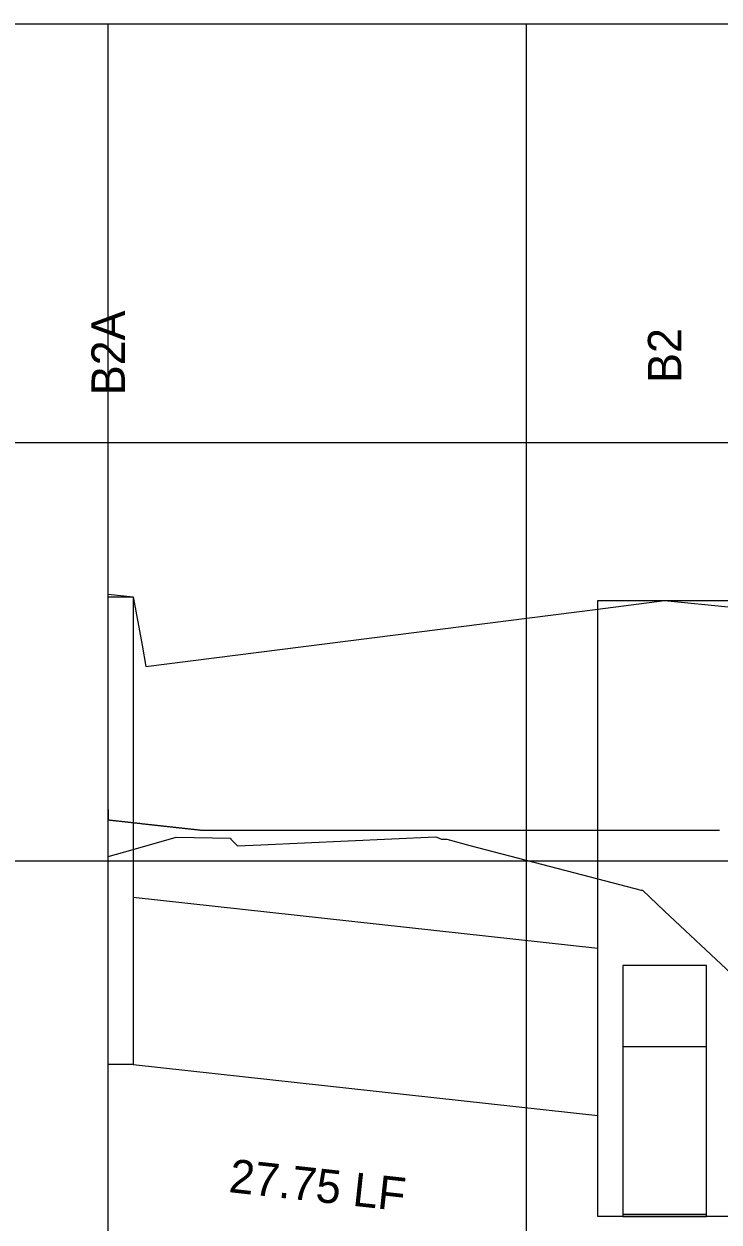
# Model space of a CAD drawing. Extents: x 2254979 to 2278074, y 13790855 to 13792793.
# Drawn here: x 2276869.4 to 2276910.9, y 13792721 to 13792792.6 of the extents above; entities that cross this region are included whole.
import ezdxf

# ---------------------------------------------------------------- set-up
doc = ezdxf.new("R2010")
doc.units = 0
for name, color, linetype in [('blank4', 7, 'Continuous'), ('BORD_grid_bottom_major_5int', 7, 'Continuous'), ('D_DRN_PROF_HGL', 7, 'Continuous'), ('D_PROF_1', 7, 'Continuous'), ('D_PROF_NOTES_1', 7, 'Continuous'), ('Drain_PipeInside', 7, 'Continuous'), ('E_Terrain', 7, 'Continuous'), ('Inlet', 7, 'Continuous'), ('z - Construction', 7, 'Continuous')]:
    doc.layers.add(name, color=color, linetype=linetype)

msp = doc.modelspace()

# ---------------------------------------------------------------- linework, layer by layer
at = {"layer": 'blank4'}
msp.add_lwpolyline([(2276874.404, 13792692.599), (2276874.404, 13792767.599), (2276944.852, 13792767.599), (2276944.852, 13792692.599)], close=True, dxfattribs=at)
at = {"layer": 'BORD_grid_bottom_major_5int'}
for p, q in [((2276749.404, 13792792.599), (2277074.404, 13792792.599)), ((2276874.404, 13792492.599), (2276874.404, 13792792.599)), ((2276899.404, 13792492.599), (2276899.404, 13792792.599)), ((2276749.404, 13792767.599), (2277074.404, 13792767.599)), ((2276749.404, 13792742.599), (2277074.404, 13792742.599))]:
    msp.add_line(p, q, dxfattribs=at)
at = {"layer": 'D_DRN_PROF_HGL'}
msp.add_line((2276907.654, 13792744.435), (2276907.654, 13792744.435), dxfattribs=at)
for points in [[(2276874.404, 13792745.671), (2276874.404, 13792745.042), (2276874.411, 13792745.046), (2276874.457, 13792745.041), (2276874.503, 13792745.036), (2276874.548, 13792745.031), (2276874.594, 13792745.026), (2276874.639, 13792745.021), (2276874.685, 13792745.016), (2276874.73, 13792745.011), (2276874.776, 13792745.006), (2276874.821, 13792745.001), (2276874.867, 13792744.996), (2276874.912, 13792744.991), (2276874.958, 13792744.986), (2276875.003, 13792744.981), (2276875.049, 13792744.975), (2276875.095, 13792744.97), (2276875.14, 13792744.965), (2276875.186, 13792744.96), (2276875.231, 13792744.955), (2276875.277, 13792744.95), (2276875.322, 13792744.945), (2276875.368, 13792744.94), (2276875.413, 13792744.935), (2276875.459, 13792744.93), (2276875.504, 13792744.925), (2276875.55, 13792744.92), (2276875.595, 13792744.915), (2276875.641, 13792744.91), (2276875.687, 13792744.905), (2276875.732, 13792744.9), (2276875.778, 13792744.895), (2276875.823, 13792744.89), (2276875.869, 13792744.885), (2276875.914, 13792744.88), (2276875.96, 13792744.875), (2276876.005, 13792744.87), (2276876.051, 13792744.865), (2276876.096, 13792744.86), (2276876.142, 13792744.855), (2276876.187, 13792744.85), (2276876.233, 13792744.845), (2276876.279, 13792744.84), (2276876.324, 13792744.835), (2276876.37, 13792744.83), (2276876.415, 13792744.825), (2276876.461, 13792744.82), (2276876.506, 13792744.815), (2276876.552, 13792744.81), (2276876.597, 13792744.805), (2276876.643, 13792744.8), (2276876.688, 13792744.795), (2276876.734, 13792744.79), (2276876.779, 13792744.785), (2276876.825, 13792744.78), (2276876.871, 13792744.775), (2276876.916, 13792744.77), (2276876.962, 13792744.765), (2276877.007, 13792744.76), (2276877.053, 13792744.755), (2276877.098, 13792744.75), (2276877.144, 13792744.745), (2276877.189, 13792744.74), (2276877.235, 13792744.735), (2276877.28, 13792744.73), (2276877.326, 13792744.725), (2276877.371, 13792744.72), (2276877.417, 13792744.715), (2276877.463, 13792744.71), (2276877.508, 13792744.704), (2276877.554, 13792744.699), (2276877.599, 13792744.694), (2276877.645, 13792744.689), (2276877.69, 13792744.684), (2276877.736, 13792744.679), (2276877.781, 13792744.674), (2276877.827, 13792744.669), (2276877.872, 13792744.664), (2276877.918, 13792744.659), (2276877.963, 13792744.654), (2276878.009, 13792744.649), (2276878.055, 13792744.644), (2276878.1, 13792744.639), (2276878.146, 13792744.634), (2276878.191, 13792744.629), (2276878.237, 13792744.624), (2276878.282, 13792744.619), (2276878.328, 13792744.614), (2276878.373, 13792744.609), (2276878.419, 13792744.604), (2276878.464, 13792744.599), (2276878.51, 13792744.594), (2276878.555, 13792744.589), (2276878.601, 13792744.584), (2276878.647, 13792744.579), (2276878.692, 13792744.574), (2276878.738, 13792744.569), (2276878.783, 13792744.564), (2276878.829, 13792744.559), (2276878.874, 13792744.554), (2276878.92, 13792744.549), (2276878.965, 13792744.544), (2276879.011, 13792744.539), (2276879.056, 13792744.534), (2276879.102, 13792744.529), (2276879.147, 13792744.524), (2276879.193, 13792744.519), (2276879.239, 13792744.514), (2276879.284, 13792744.509), (2276879.33, 13792744.504), (2276879.375, 13792744.499), (2276879.421, 13792744.494), (2276879.466, 13792744.489), (2276879.512, 13792744.484), (2276879.557, 13792744.479), (2276879.603, 13792744.474), (2276879.648, 13792744.469), (2276879.694, 13792744.464), (2276879.739, 13792744.459), (2276879.785, 13792744.454), (2276879.831, 13792744.449), (2276879.876, 13792744.444), (2276879.922, 13792744.44), (2276879.967, 13792744.44), (2276880.013, 13792744.44), (2276880.058, 13792744.44), (2276880.104, 13792744.44), (2276880.149, 13792744.44), (2276880.195, 13792744.44), (2276880.24, 13792744.44), (2276880.286, 13792744.44), (2276880.331, 13792744.44), (2276880.377, 13792744.44), (2276880.423, 13792744.44), (2276880.468, 13792744.44), (2276880.514, 13792744.44), (2276880.559, 13792744.44), (2276880.605, 13792744.44), (2276880.65, 13792744.44), (2276880.696, 13792744.44), (2276880.741, 13792744.44), (2276880.787, 13792744.44), (2276880.832, 13792744.44), (2276880.878, 13792744.44), (2276880.923, 13792744.44), (2276880.969, 13792744.44), (2276881.015, 13792744.44), (2276881.06, 13792744.44), (2276881.106, 13792744.44), (2276881.151, 13792744.44), (2276881.197, 13792744.44), (2276881.242, 13792744.44), (2276881.288, 13792744.44), (2276881.333, 13792744.44), (2276881.379, 13792744.44), (2276881.424, 13792744.44), (2276881.47, 13792744.44), (2276881.515, 13792744.44), (2276881.561, 13792744.44), (2276881.607, 13792744.44), (2276881.652, 13792744.44), (2276881.698, 13792744.44), (2276881.743, 13792744.44), (2276881.789, 13792744.44), (2276881.834, 13792744.44), (2276881.88, 13792744.44), (2276881.925, 13792744.44), (2276881.971, 13792744.44), (2276882.016, 13792744.44), (2276882.062, 13792744.44), (2276882.107, 13792744.44), (2276882.153, 13792744.44), (2276882.199, 13792744.44), (2276882.244, 13792744.44), (2276882.29, 13792744.44), (2276882.335, 13792744.44), (2276882.381, 13792744.44), (2276882.426, 13792744.44), (2276882.472, 13792744.44), (2276882.517, 13792744.44), (2276882.563, 13792744.44), (2276882.608, 13792744.44), (2276882.654, 13792744.44), (2276882.699, 13792744.44), (2276882.745, 13792744.44), (2276882.791, 13792744.44), (2276882.836, 13792744.44), (2276882.882, 13792744.44), (2276882.927, 13792744.44), (2276882.973, 13792744.44), (2276883.018, 13792744.44), (2276883.064, 13792744.44), (2276883.109, 13792744.44), (2276883.155, 13792744.44), (2276883.2, 13792744.44), (2276883.246, 13792744.44), (2276883.291, 13792744.44), (2276883.337, 13792744.44), (2276883.383, 13792744.44), (2276883.428, 13792744.44), (2276883.474, 13792744.44), (2276883.519, 13792744.44), (2276883.565, 13792744.44), (2276883.61, 13792744.44), (2276883.656, 13792744.44), (2276883.701, 13792744.44), (2276883.747, 13792744.44), (2276883.792, 13792744.44), (2276883.838, 13792744.44), (2276883.883, 13792744.44), (2276883.929, 13792744.44), (2276883.975, 13792744.44), (2276884.02, 13792744.44), (2276884.066, 13792744.44), (2276884.111, 13792744.44), (2276884.157, 13792744.44), (2276884.202, 13792744.44), (2276884.248, 13792744.44), (2276884.293, 13792744.44), (2276884.339, 13792744.44), (2276884.384, 13792744.44), (2276884.43, 13792744.439), (2276884.475, 13792744.439), (2276884.521, 13792744.439), (2276884.567, 13792744.439), (2276884.612, 13792744.439), (2276884.658, 13792744.439), (2276884.703, 13792744.439), (2276884.749, 13792744.439), (2276884.794, 13792744.439), (2276884.84, 13792744.439), (2276884.885, 13792744.439), (2276884.931, 13792744.439), (2276884.976, 13792744.439), (2276885.022, 13792744.439), (2276885.067, 13792744.439), (2276885.113, 13792744.439), (2276885.159, 13792744.439), (2276885.204, 13792744.439), (2276885.25, 13792744.439), (2276885.295, 13792744.439), (2276885.341, 13792744.439), (2276885.386, 13792744.439), (2276885.432, 13792744.439), (2276885.477, 13792744.439), (2276885.523, 13792744.439), (2276885.568, 13792744.439), (2276885.614, 13792744.439), (2276885.659, 13792744.439), (2276885.705, 13792744.439), (2276885.75, 13792744.439), (2276885.796, 13792744.439), (2276885.842, 13792744.439), (2276885.887, 13792744.439), (2276885.933, 13792744.439), (2276885.978, 13792744.439), (2276886.024, 13792744.439), (2276886.069, 13792744.439), (2276886.115, 13792744.439), (2276886.16, 13792744.439), (2276886.206, 13792744.439), (2276886.251, 13792744.439), (2276886.297, 13792744.439), (2276886.342, 13792744.439), (2276886.388, 13792744.439), (2276886.434, 13792744.439), (2276886.479, 13792744.439), (2276886.525, 13792744.439), (2276886.57, 13792744.439), (2276886.616, 13792744.439), (2276886.661, 13792744.439), (2276886.707, 13792744.439), (2276886.752, 13792744.439), (2276886.798, 13792744.439), (2276886.843, 13792744.439), (2276886.889, 13792744.439), (2276886.934, 13792744.439), (2276886.98, 13792744.439), (2276887.026, 13792744.439), (2276887.071, 13792744.439), (2276887.117, 13792744.439), (2276887.162, 13792744.439), (2276887.208, 13792744.439), (2276887.253, 13792744.439), (2276887.299, 13792744.439), (2276887.344, 13792744.439), (2276887.39, 13792744.439), (2276887.435, 13792744.439), (2276887.481, 13792744.439), (2276887.526, 13792744.439), (2276887.572, 13792744.439), (2276887.618, 13792744.439), (2276887.663, 13792744.439), (2276887.709, 13792744.439), (2276887.754, 13792744.439), (2276887.8, 13792744.439), (2276887.845, 13792744.439), (2276887.891, 13792744.439), (2276887.936, 13792744.439), (2276887.982, 13792744.439), (2276888.027, 13792744.439), (2276888.073, 13792744.439), (2276888.118, 13792744.439), (2276888.164, 13792744.439), (2276888.21, 13792744.439), (2276888.255, 13792744.439), (2276888.301, 13792744.439), (2276888.346, 13792744.439), (2276888.392, 13792744.439), (2276888.437, 13792744.439), (2276888.483, 13792744.439), (2276888.528, 13792744.439), (2276888.574, 13792744.439), (2276888.619, 13792744.439), (2276888.665, 13792744.439), (2276888.71, 13792744.439), (2276888.756, 13792744.439), (2276888.802, 13792744.439), (2276888.847, 13792744.439), (2276888.893, 13792744.439), (2276888.938, 13792744.439), (2276888.984, 13792744.439), (2276889.029, 13792744.439), (2276889.075, 13792744.439), (2276889.12, 13792744.439), (2276889.166, 13792744.439), (2276889.211, 13792744.439), (2276889.257, 13792744.439), (2276889.302, 13792744.439), (2276889.348, 13792744.438), (2276889.394, 13792744.438), (2276889.439, 13792744.438), (2276889.485, 13792744.438), (2276889.53, 13792744.438), (2276889.576, 13792744.438), (2276889.621, 13792744.438), (2276889.667, 13792744.438), (2276889.712, 13792744.438), (2276889.758, 13792744.438), (2276889.803, 13792744.438), (2276889.849, 13792744.438), (2276889.894, 13792744.438), (2276889.94, 13792744.438), (2276889.986, 13792744.438), (2276890.031, 13792744.438), (2276890.077, 13792744.438), (2276890.122, 13792744.438), (2276890.168, 13792744.438), (2276890.213, 13792744.438), (2276890.259, 13792744.438), (2276890.304, 13792744.438), (2276890.35, 13792744.438), (2276890.395, 13792744.438), (2276890.441, 13792744.438), (2276890.486, 13792744.438), (2276890.532, 13792744.438), (2276890.578, 13792744.438), (2276890.623, 13792744.438), (2276890.669, 13792744.438), (2276890.714, 13792744.438), (2276890.76, 13792744.438), (2276890.805, 13792744.438), (2276890.851, 13792744.438), (2276890.896, 13792744.438), (2276890.942, 13792744.438), (2276890.987, 13792744.438), (2276891.033, 13792744.438), (2276891.078, 13792744.438), (2276891.124, 13792744.438), (2276891.17, 13792744.438), (2276891.215, 13792744.438), (2276891.261, 13792744.438), (2276891.306, 13792744.438), (2276891.352, 13792744.438), (2276891.397, 13792744.438), (2276891.443, 13792744.438), (2276891.488, 13792744.438), (2276891.534, 13792744.438), (2276891.579, 13792744.438), (2276891.625, 13792744.438), (2276891.67, 13792744.438), (2276891.716, 13792744.438), (2276891.762, 13792744.438), (2276891.807, 13792744.438), (2276891.853, 13792744.438), (2276891.898, 13792744.438), (2276891.944, 13792744.438), (2276891.989, 13792744.438), (2276892.035, 13792744.438), (2276892.08, 13792744.438), (2276892.126, 13792744.438), (2276892.171, 13792744.438), (2276892.217, 13792744.438), (2276892.262, 13792744.438), (2276892.308, 13792744.438), (2276892.354, 13792744.438), (2276892.399, 13792744.438), (2276892.445, 13792744.438), (2276892.49, 13792744.438), (2276892.536, 13792744.438), (2276892.581, 13792744.438), (2276892.627, 13792744.438), (2276892.672, 13792744.438), (2276892.718, 13792744.438), (2276892.763, 13792744.438), (2276892.809, 13792744.438), (2276892.854, 13792744.438), (2276892.9, 13792744.438), (2276892.946, 13792744.438), (2276892.991, 13792744.438), (2276893.037, 13792744.438), (2276893.082, 13792744.438), (2276893.128, 13792744.438), (2276893.173, 13792744.438), (2276893.219, 13792744.438), (2276893.264, 13792744.438), (2276893.31, 13792744.438), (2276893.355, 13792744.438), (2276893.401, 13792744.438), (2276893.446, 13792744.438), (2276893.492, 13792744.438), (2276893.538, 13792744.438), (2276893.583, 13792744.438), (2276893.629, 13792744.438), (2276893.674, 13792744.438), (2276893.72, 13792744.438), (2276893.765, 13792744.438), (2276893.811, 13792744.438), (2276893.856, 13792744.438), (2276893.902, 13792744.438), (2276893.947, 13792744.438), (2276893.993, 13792744.438), (2276894.038, 13792744.438), (2276894.084, 13792744.438), (2276894.13, 13792744.438), (2276894.175, 13792744.438), (2276894.221, 13792744.438), (2276894.266, 13792744.437), (2276894.312, 13792744.437), (2276894.357, 13792744.437), (2276894.403, 13792744.437), (2276894.448, 13792744.437), (2276894.494, 13792744.437), (2276894.539, 13792744.437), (2276894.585, 13792744.437), (2276894.63, 13792744.437), (2276894.676, 13792744.437), (2276894.722, 13792744.437), (2276894.767, 13792744.437), (2276894.813, 13792744.437), (2276894.858, 13792744.437), (2276894.904, 13792744.437), (2276894.949, 13792744.437), (2276894.995, 13792744.437), (2276895.04, 13792744.437), (2276895.086, 13792744.437), (2276895.131, 13792744.437), (2276895.177, 13792744.437), (2276895.222, 13792744.437), (2276895.268, 13792744.437), (2276895.314, 13792744.437), (2276895.359, 13792744.437), (2276895.405, 13792744.437), (2276895.45, 13792744.437), (2276895.496, 13792744.437), (2276895.541, 13792744.437), (2276895.587, 13792744.437), (2276895.632, 13792744.437), (2276895.678, 13792744.437), (2276895.723, 13792744.437), (2276895.769, 13792744.437), (2276895.814, 13792744.437), (2276895.86, 13792744.437), (2276895.906, 13792744.437), (2276895.951, 13792744.437), (2276895.997, 13792744.437), (2276896.042, 13792744.437), (2276896.088, 13792744.437), (2276896.133, 13792744.437), (2276896.179, 13792744.437), (2276896.224, 13792744.437), (2276896.27, 13792744.437), (2276896.315, 13792744.437), (2276896.361, 13792744.437), (2276896.406, 13792744.437), (2276896.452, 13792744.437), (2276896.498, 13792744.437), (2276896.543, 13792744.437), (2276896.589, 13792744.437), (2276896.634, 13792744.437), (2276896.68, 13792744.437), (2276896.725, 13792744.437), (2276896.771, 13792744.437), (2276896.816, 13792744.437), (2276896.862, 13792744.437), (2276896.907, 13792744.437), (2276896.953, 13792744.437), (2276896.998, 13792744.437), (2276897.044, 13792744.437), (2276897.09, 13792744.437), (2276897.135, 13792744.437), (2276897.181, 13792744.437), (2276897.226, 13792744.437), (2276897.272, 13792744.437), (2276897.317, 13792744.437), (2276897.363, 13792744.437), (2276897.408, 13792744.437), (2276897.454, 13792744.437), (2276897.499, 13792744.437), (2276897.545, 13792744.437), (2276897.59, 13792744.437), (2276897.636, 13792744.437), (2276897.682, 13792744.437), (2276897.727, 13792744.437), (2276897.773, 13792744.437), (2276897.818, 13792744.437), (2276897.864, 13792744.437), (2276897.909, 13792744.437), (2276897.955, 13792744.437), (2276898, 13792744.437), (2276898.046, 13792744.437), (2276898.091, 13792744.437), (2276898.137, 13792744.437), (2276898.182, 13792744.437), (2276898.228, 13792744.437), (2276898.274, 13792744.437), (2276898.319, 13792744.437), (2276898.365, 13792744.437), (2276898.41, 13792744.437), (2276898.456, 13792744.437), (2276898.501, 13792744.437), (2276898.547, 13792744.437), (2276898.592, 13792744.437), (2276898.638, 13792744.437), (2276898.683, 13792744.437), (2276898.729, 13792744.437), (2276898.774, 13792744.437), (2276898.82, 13792744.437), (2276898.866, 13792744.437), (2276898.911, 13792744.437), (2276898.957, 13792744.437), (2276899.002, 13792744.437), (2276899.048, 13792744.437), (2276899.093, 13792744.437), (2276899.139, 13792744.437), (2276899.184, 13792744.436), (2276899.23, 13792744.436), (2276899.275, 13792744.436), (2276899.321, 13792744.436), (2276899.366, 13792744.436), (2276899.412, 13792744.436), (2276899.458, 13792744.436), (2276899.503, 13792744.436), (2276899.549, 13792744.436), (2276899.594, 13792744.436), (2276899.64, 13792744.436), (2276899.685, 13792744.436), (2276899.731, 13792744.436), (2276899.776, 13792744.436), (2276899.822, 13792744.436), (2276899.867, 13792744.436), (2276899.913, 13792744.436), (2276899.958, 13792744.436), (2276900.004, 13792744.436), (2276900.05, 13792744.436), (2276900.095, 13792744.436), (2276900.141, 13792744.436), (2276900.186, 13792744.436), (2276900.232, 13792744.436), (2276900.277, 13792744.436), (2276900.323, 13792744.436), (2276900.368, 13792744.436), (2276900.414, 13792744.436), (2276900.459, 13792744.436), (2276900.505, 13792744.436), (2276900.55, 13792744.436), (2276900.596, 13792744.436), (2276900.642, 13792744.436), (2276900.687, 13792744.436), (2276900.733, 13792744.436), (2276900.778, 13792744.436), (2276900.824, 13792744.436), (2276900.869, 13792744.436), (2276900.915, 13792744.436), (2276900.96, 13792744.436), (2276901.006, 13792744.436), (2276901.051, 13792744.436), (2276901.097, 13792744.436), (2276901.142, 13792744.436), (2276901.188, 13792744.436), (2276901.233, 13792744.436), (2276901.279, 13792744.436), (2276901.325, 13792744.436), (2276901.37, 13792744.436), (2276901.416, 13792744.436), (2276901.461, 13792744.436), (2276901.507, 13792744.436), (2276901.552, 13792744.436), (2276901.598, 13792744.436), (2276901.643, 13792744.436), (2276901.689, 13792744.436), (2276901.734, 13792744.436), (2276901.78, 13792744.436), (2276901.825, 13792744.436), (2276901.871, 13792744.436), (2276901.917, 13792744.436), (2276901.962, 13792744.436), (2276902.008, 13792744.436), (2276902.053, 13792744.436), (2276902.099, 13792744.436), (2276902.144, 13792744.436), (2276902.19, 13792744.436), (2276902.235, 13792744.436), (2276902.281, 13792744.436), (2276902.326, 13792744.436), (2276902.372, 13792744.436), (2276902.417, 13792744.436), (2276902.463, 13792744.436), (2276902.509, 13792744.436), (2276902.554, 13792744.436), (2276902.6, 13792744.436), (2276902.645, 13792744.436), (2276902.691, 13792744.436), (2276902.736, 13792744.436), (2276902.782, 13792744.436), (2276902.827, 13792744.436), (2276902.873, 13792744.436), (2276902.918, 13792744.436), (2276902.964, 13792744.436), (2276903.009, 13792744.436), (2276903.055, 13792744.436), (2276903.101, 13792744.436), (2276903.146, 13792744.436), (2276903.192, 13792744.436), (2276903.237, 13792744.436), (2276903.283, 13792744.436), (2276903.328, 13792744.436), (2276903.374, 13792744.436), (2276903.419, 13792744.436), (2276903.465, 13792744.436), (2276903.51, 13792744.436), (2276903.556, 13792744.436), (2276903.601, 13792744.436), (2276903.647, 13792744.436), (2276903.693, 13792744.436), (2276903.738, 13792744.436), (2276903.784, 13792744.436), (2276903.829, 13792744.436), (2276903.875, 13792744.436), (2276903.92, 13792744.436), (2276903.966, 13792744.436), (2276904.011, 13792744.435), (2276904.057, 13792744.435), (2276904.102, 13792744.435), (2276904.148, 13792744.435), (2276904.193, 13792744.435), (2276904.239, 13792744.435), (2276904.285, 13792744.435), (2276904.33, 13792744.435), (2276904.376, 13792744.435), (2276904.421, 13792744.435), (2276904.467, 13792744.435), (2276904.512, 13792744.435), (2276904.558, 13792744.435), (2276904.603, 13792744.435), (2276904.649, 13792744.435), (2276904.694, 13792744.435), (2276904.74, 13792744.435), (2276904.785, 13792744.435), (2276904.831, 13792744.435), (2276904.877, 13792744.435), (2276904.922, 13792744.435), (2276904.968, 13792744.435), (2276905.013, 13792744.435), (2276905.059, 13792744.435), (2276905.104, 13792744.435), (2276905.15, 13792744.435), (2276905.195, 13792744.435), (2276905.241, 13792744.435), (2276905.286, 13792744.435), (2276905.332, 13792744.435), (2276905.377, 13792744.435), (2276905.423, 13792744.435), (2276905.469, 13792744.435), (2276905.514, 13792744.435), (2276905.56, 13792744.435), (2276905.605, 13792744.435), (2276905.651, 13792744.435), (2276905.696, 13792744.435), (2276905.742, 13792744.435), (2276905.787, 13792744.435), (2276905.833, 13792744.435), (2276905.878, 13792744.435), (2276905.924, 13792744.435), (2276905.969, 13792744.435), (2276906.015, 13792744.435), (2276906.061, 13792744.435), (2276906.106, 13792744.435), (2276906.152, 13792744.435), (2276906.197, 13792744.435), (2276906.243, 13792744.435), (2276906.288, 13792744.435), (2276906.334, 13792744.435), (2276906.379, 13792744.435), (2276906.425, 13792744.435), (2276906.47, 13792744.435), (2276906.516, 13792744.435), (2276906.561, 13792744.435), (2276906.607, 13792744.435), (2276906.653, 13792744.435), (2276906.698, 13792744.435), (2276906.744, 13792744.435), (2276906.789, 13792744.435), (2276906.835, 13792744.435), (2276906.88, 13792744.435), (2276906.926, 13792744.435), (2276906.971, 13792744.435), (2276907.017, 13792744.435), (2276907.062, 13792744.435), (2276907.108, 13792744.435), (2276907.153, 13792744.435), (2276907.199, 13792744.435), (2276907.245, 13792744.435), (2276907.29, 13792744.435), (2276907.336, 13792744.435), (2276907.381, 13792744.435), (2276907.427, 13792744.435), (2276907.472, 13792744.435), (2276907.518, 13792744.435), (2276907.563, 13792744.435), (2276907.609, 13792744.435), (2276907.654, 13792744.435)], [(2276907.654, 13792744.435), (2276907.7, 13792744.435), (2276907.746, 13792744.435), (2276907.791, 13792744.435), (2276907.837, 13792744.435), (2276907.882, 13792744.435), (2276907.928, 13792744.435), (2276907.974, 13792744.435), (2276908.019, 13792744.435), (2276908.065, 13792744.435), (2276908.111, 13792744.435), (2276908.156, 13792744.435), (2276908.202, 13792744.435), (2276908.247, 13792744.435), (2276908.293, 13792744.435), (2276908.339, 13792744.435), (2276908.384, 13792744.435), (2276908.43, 13792744.435), (2276908.475, 13792744.435), (2276908.521, 13792744.435), (2276908.567, 13792744.435), (2276908.612, 13792744.435), (2276908.658, 13792744.435), (2276908.704, 13792744.435), (2276908.749, 13792744.435), (2276908.795, 13792744.435), (2276908.84, 13792744.435), (2276908.886, 13792744.435), (2276908.932, 13792744.435), (2276908.977, 13792744.435), (2276909.023, 13792744.435), (2276909.068, 13792744.435), (2276909.114, 13792744.435), (2276909.16, 13792744.435), (2276909.205, 13792744.435), (2276909.251, 13792744.435), (2276909.297, 13792744.435), (2276909.342, 13792744.435), (2276909.388, 13792744.435), (2276909.433, 13792744.435), (2276909.479, 13792744.435), (2276909.525, 13792744.435), (2276909.57, 13792744.436), (2276909.616, 13792744.436), (2276909.661, 13792744.436), (2276909.707, 13792744.436), (2276909.753, 13792744.436), (2276909.798, 13792744.436), (2276909.844, 13792744.436), (2276909.89, 13792744.436), (2276909.935, 13792744.436), (2276909.981, 13792744.436), (2276910.026, 13792744.436), (2276910.072, 13792744.436), (2276910.118, 13792744.436), (2276910.163, 13792744.436), (2276910.209, 13792744.436), (2276910.254, 13792744.436), (2276910.3, 13792744.436), (2276910.346, 13792744.436), (2276910.391, 13792744.436), (2276910.437, 13792744.436), (2276910.483, 13792744.436), (2276910.528, 13792744.436), (2276910.574, 13792744.436), (2276910.619, 13792744.436), (2276910.665, 13792744.436), (2276910.711, 13792744.436), (2276910.756, 13792744.436), (2276910.802, 13792744.436), (2276910.847, 13792744.436), (2276910.893, 13792744.436), (2276910.939, 13792744.436)]]:
    msp.add_lwpolyline(points, dxfattribs=at)
at = {"layer": 'D_PROF_1'}
msp.add_lwpolyline([(2276874.404, 13792758.529), (2276875.904, 13792758.379), (2276875.904, 13792758.379), (2276875.904, 13792758.379), (2276876.425, 13792755.486), (2276876.654, 13792754.213), (2276903.654, 13792757.639), (2276903.654, 13792757.639), (2276907.654, 13792758.146), (2276907.654, 13792758.146), (2276907.654, 13792758.146), (2276911.654, 13792757.746)], dxfattribs=at)
at = {"layer": 'Drain_PipeInside'}
for p, q in [((2276875.904, 13792740.429), (2276903.654, 13792737.376)), ((2276875.904, 13792730.429), (2276903.654, 13792727.376))]:
    msp.add_line(p, q, dxfattribs=at)
for points in [[(2276905.154, 13792721.349), (2276910.154, 13792721.349), (2276910.154, 13792736.349), (2276905.154, 13792736.349)], [(2276905.154, 13792721.484), (2276910.154, 13792721.484), (2276910.154, 13792731.484), (2276905.154, 13792731.484)]]:
    msp.add_lwpolyline(points, close=True, dxfattribs=at)
at = {"layer": 'E_Terrain'}
msp.add_lwpolyline([(2276874.404, 13792742.863), (2276875.904, 13792743.286), (2276875.904, 13792743.286), (2276878.468, 13792744.007), (2276881.702, 13792743.955), (2276881.738, 13792743.889), (2276882.13, 13792743.492), (2276883.532, 13792743.551), (2276893.956, 13792744.029), (2276894.038, 13792744.023), (2276894.323, 13792743.891), (2276894.646, 13792743.891), (2276896.019, 13792743.523), (2276903.654, 13792741.525), (2276903.654, 13792741.525), (2276906.257, 13792740.844), (2276906.329, 13792740.844), (2276907.654, 13792739.6), (2276907.654, 13792739.6), (2276911.654, 13792735.846)], dxfattribs=at)
at = {"layer": 'Inlet'}
for points in [[(2276874.404, 13792758.379), (2276875.904, 13792758.379), (2276875.904, 13792730.429), (2276874.404, 13792730.429)], [(2276903.654, 13792758.146), (2276911.654, 13792758.146), (2276911.654, 13792721.349), (2276903.654, 13792721.349)]]:
    msp.add_lwpolyline(points, close=True, dxfattribs=at)
at = {"layer": 'z - Construction'}
msp.add_line((2276874.404, 13792742.599), (2276944.852, 13792742.599), dxfattribs=at)

# ---------------------------------------------------------------- texts
at = {"layer": 'D_PROF_NOTES_1'}
for s, rotation, p in [('B2A', 90, (2276875.404, 13792770.42)), ('B2', 90, (2276908.654, 13792771.155)), ('27.75 LF', 353.7227, (2276881.562, 13792722.812))]:
    msp.add_text(s, height=2, rotation=rotation, dxfattribs=at).set_placement(p)

doc.saveas('drawing.dxf')
